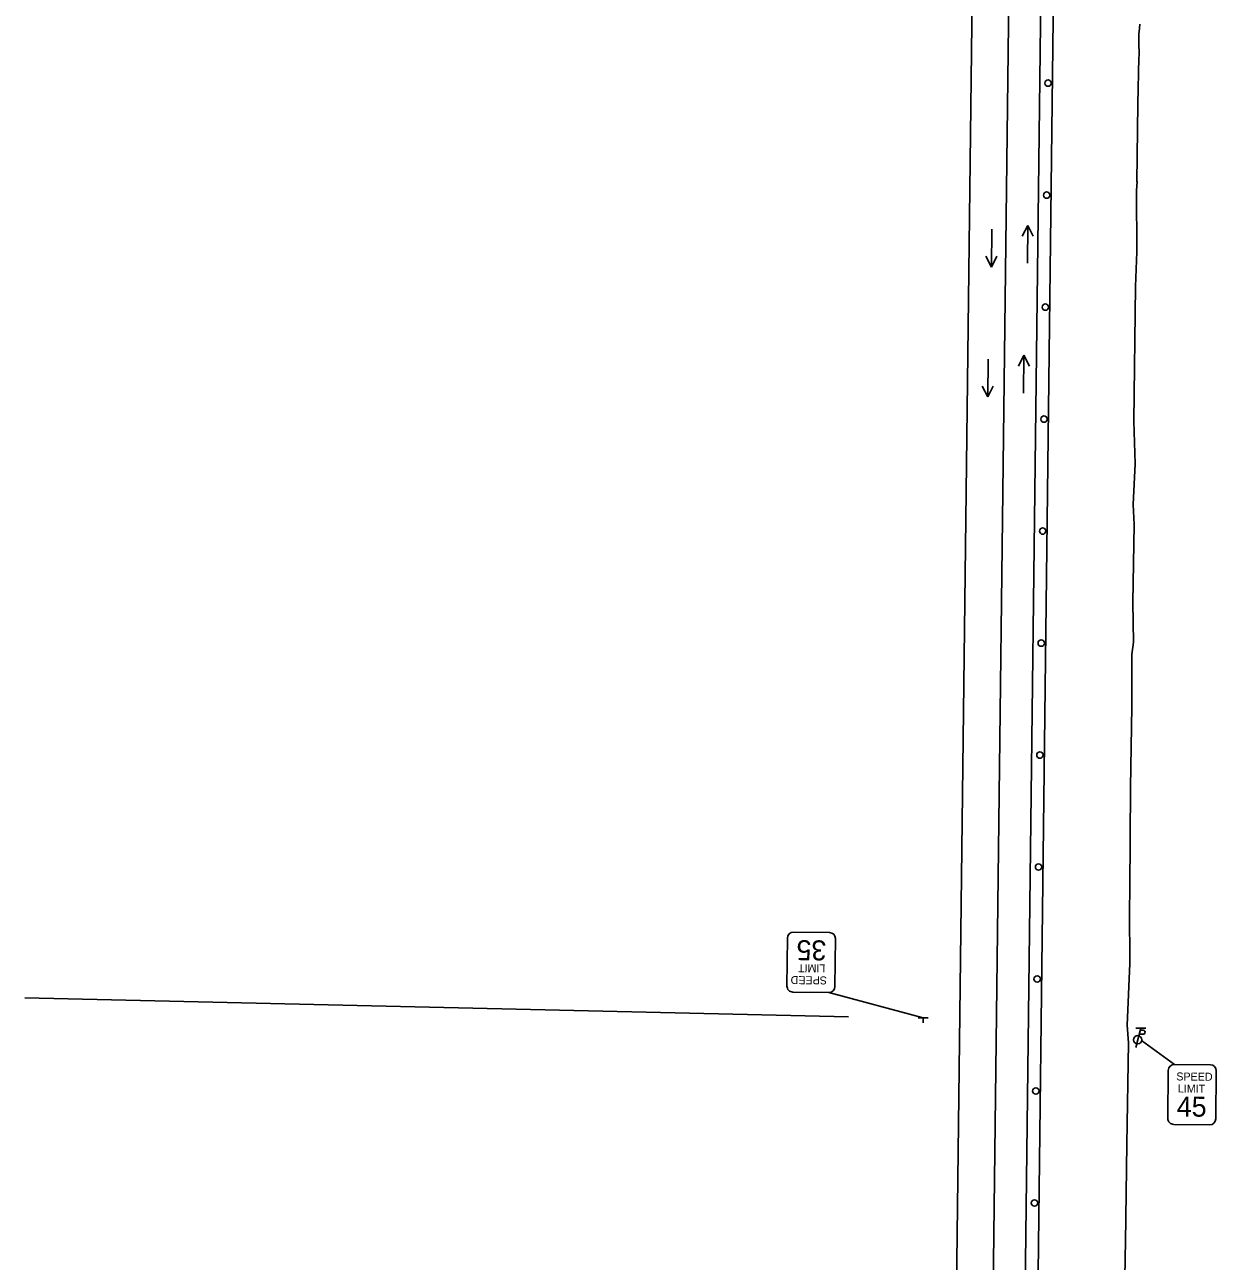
# Model space of a CAD drawing. Extents: x 1650647 to 1653016, y 602856 to 611467.
# Drawn here: x 1652241.2 to 1652613.7, y 607719.3 to 608105.8 of the extents above; entities that cross this region are included whole.
import ezdxf

# ---------------------------------------------------------------- set-up
doc = ezdxf.new("R2010")
doc.units = 0
for name, color, linetype in [('CM_Corridor_Design', 7, 'Continuous'), ('DT_X_Break_Line', 7, 'Continuous'), ('DT_X_Contour_Major', 7, 'Continuous'), ('MD_P_Drive_MatchLine', 7, 'Continuous'), ('MD_P_Intersection_MatchLine', 7, 'Continuous'), ('PF_X_Ground_Line', 7, 'Continuous'), ('PV_P_EOP', 7, 'Continuous'), ('PV_X_EOP', 7, 'Continuous'), ('SC_Scratch1', 7, 'Continuous'), ('UT_X_Gas', 7, 'Continuous'), ('UT_X_Water', 7, 'Continuous')]:
    doc.layers.add(name, color=color, linetype=linetype)

msp = doc.modelspace()

# ---------------------------------------------------------------- linework, layer by layer
at = {"layer": 'CM_Corridor_Design'}
for p, q in [((1652543.36, 608030.04), (1652543.49, 608041.89)), ((1652554.78, 608043.06), (1652553.02, 608039.7)), ((1652554.78, 608043.06), (1652554.65, 608031.2)), ((1652554.78, 608043.06), (1652556.47, 608039.66)), ((1652543.36, 608030.04), (1652541.68, 608033.43)), ((1652543.36, 608030.04), (1652545.12, 608033.39)), ((1652542.22, 607989.43), (1652542.35, 608001.29)), ((1652553.56, 608002.46), (1652551.8, 607999.1)), ((1652553.56, 608002.46), (1652553.43, 607990.6)), ((1652553.56, 608002.46), (1652555.25, 607999.06)), ((1652542.22, 607989.43), (1652540.54, 607992.83)), ((1652542.22, 607989.43), (1652543.98, 607992.79))]:
    msp.add_line(p, q, dxfattribs=at)
at = {"layer": 'DT_X_Break_Line'}
for centre in [(1652561.08, 608087.52), (1652560.65, 608052.52), (1652560.22, 608017.51), (1652559.81, 607982.52), (1652559.39, 607947.53), (1652558.96, 607912.51), (1652558.54, 607877.53), (1652558.12, 607842.53), (1652557.69, 607807.54), (1652557.27, 607772.54), (1652556.85, 607737.54)]:
    msp.add_circle(centre, 1, dxfattribs=at)
at = {"layer": 'DT_X_Contour_Major'}
for points in [[(1652553.06, 607306.57), (1652569.14, 608647.46)], [(1652584.49, 607679.21), (1652585.3, 607725.82), (1652585.24, 607725.33), (1652585.67, 607755.96), (1652586.21, 607787.57), (1652585.81, 607793.1), (1652586.61, 607812.41), (1652586.53, 607829.02), (1652586.66, 607835.54), (1652586.86, 607867.34), (1652587.28, 607892.75), (1652587.25, 607908.98), (1652587.75, 607912.8), (1652587.55, 607925.17), (1652588.03, 607949.63), (1652587.69, 607955.8), (1652588.27, 607968.59), (1652587.9, 607981.83), (1652588.43, 608023.95), (1652588.83, 608034.79), (1652588.7, 608053.93), (1652588.9, 608056.78), (1652588.88, 608056.71), (1652589.11, 608080.96), (1652589.49, 608095.57), (1652589.58, 608096.16), (1652589.42, 608100.41), (1652589.47, 608102.82), (1652589.65, 608104.61), (1652589.77, 608105.94)], [(1652589.77, 608105.94), (1652589.65, 608104.61), (1652589.47, 608102.82), (1652589.42, 608100.41), (1652589.58, 608096.16), (1652589.49, 608095.57), (1652589.11, 608080.96), (1652588.88, 608056.71), (1652588.9, 608056.78), (1652588.7, 608053.93), (1652588.83, 608034.79), (1652588.43, 608023.95), (1652587.9, 607981.83), (1652588.27, 607968.59), (1652587.69, 607955.8), (1652588.03, 607949.63), (1652587.55, 607925.17), (1652587.75, 607912.8), (1652587.25, 607908.98), (1652587.28, 607892.75), (1652586.86, 607867.34), (1652586.66, 607835.54), (1652586.53, 607829.02), (1652586.61, 607812.41), (1652585.81, 607793.1), (1652586.21, 607787.57), (1652585.67, 607755.96), (1652585.24, 607725.33), (1652585.3, 607725.82), (1652584.49, 607679.21)]]:
    msp.add_lwpolyline(points, dxfattribs=at)
at = {"layer": 'MD_P_Drive_MatchLine'}
for p, q in [((1652522.06, 607795.4), (1652492.57, 607803.33)), ((1652590.32, 607788.35), (1652600.56, 607780.86))]:
    msp.add_line(p, q, dxfattribs=at)
at = {"layer": 'MD_P_Intersection_MatchLine'}
for p, q in [((1652591.67, 607792.14), (1652588.47, 607792.14)), ((1652590.07, 607792.14), (1652588.47, 607786.14)), ((1652589.57, 607790.26), (1652590.76, 607790.26)), ((1652589.91, 607791.54), (1652590.76, 607791.54))]:
    msp.add_line(p, q, dxfattribs=at)
msp.add_circle((1652589.11, 607788.54), 1.3, dxfattribs=at)
msp.add_arc((1652590.78, 607790.9), 0.638, 268.8767, 91.1233, dxfattribs=at)
at = {"layer": 'PF_X_Ground_Line'}
for points in [[(1652479.63, 607820.35), (1652479.47, 607805.35)], [(1652492.77, 607822.08), (1652481.53, 607822.2)], [(1652494.46, 607805.18), (1652494.63, 607820.18)], [(1652481.32, 607803.45), (1652492.57, 607803.33)], [(1652598.66, 607779), (1652598.5, 607764)], [(1652611.81, 607780.73), (1652600.56, 607780.86)], [(1652613.5, 607763.84), (1652613.66, 607778.84)], [(1652600.35, 607762.11), (1652611.6, 607761.98)]]:
    msp.add_lwpolyline(points, dxfattribs=at)
for centre, radius, start, end in [((1652481.5, 607820.33), 1.87, 89.3709, 179.3709), ((1652492.75, 607820.2), 1.87, 359.3709, 89.3709), ((1652481.34, 607805.33), 1.87, 179.3709, 269.3709), ((1652492.59, 607805.21), 1.87, 269.3709, 359.3709), ((1652600.54, 607778.98), 1.88, 89.3709, 179.3709), ((1652611.79, 607778.86), 1.88, 359.3709, 89.3709), ((1652600.37, 607763.98), 1.88, 179.3709, 269.3709), ((1652611.62, 607763.86), 1.88, 269.3709, 359.3709)]:
    msp.add_arc(centre, radius, start, end, dxfattribs=at)
at = {"layer": 'PV_P_EOP'}
msp.add_line((1652548.99, 607300.94), (1652565.26, 608647.72), dxfattribs=at)
at = {"layer": 'PV_X_EOP'}
msp.add_line((1652538.99, 607301.06), (1652555.27, 608648.04), dxfattribs=at)
at = {"layer": 'SC_Scratch1'}
msp.add_line((1652527.49, 607301.2), (1652543.76, 608647.26), dxfattribs=at)
at = {"layer": 'UT_X_Gas'}
for p, q in [((1652520.46, 607795.43), (1652523.66, 607795.36)), ((1652522.06, 607795.4), (1652522.03, 607793.8)), ((1652522.06, 607795.39), (1652522.06, 607795.39))]:
    msp.add_line(p, q, dxfattribs=at)
at = {"layer": 'UT_X_Water'}
msp.add_line((1652498.72, 607795.73), (1652241.24, 607801.7), dxfattribs=at)

# ---------------------------------------------------------------- texts
at = {"layer": 'PF_X_Ground_Line'}
for s, height, rotation, p in [('35', 6.25, 179.3709, (1652491.82, 607819.59)), ('LIMIT', 2.5, 179.3709, (1652491.49, 607812.09)), ('SPEED', 2.5, 179.3709, (1652491.97, 607808.34)), ('SPEED', 2.5, 359.3709, (1652601.16, 607775.85)), ('LIMIT', 2.5, 359.3709, (1652601.64, 607772.09)), ('45', 6.25, 359.3709, (1652601.3, 607764.6))]:
    msp.add_text(s, height=height, rotation=rotation, dxfattribs=at).set_placement(p)

doc.saveas('drawing.dxf')
